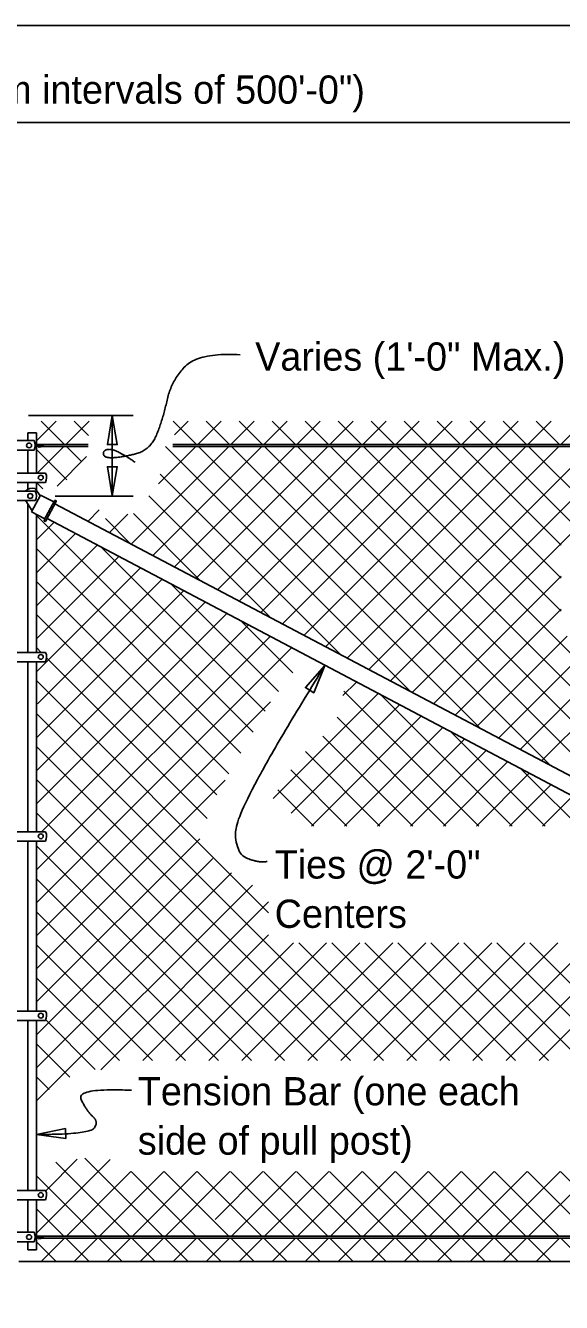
# Model space of a CAD drawing. Extents: x 0 to 72.1, y -7 to 30.
# Drawn here: x 12.41 to 16.24, y 18.9 to 28.01 of the extents above; entities that cross this region are included whole.
import ezdxf

# ---------------------------------------------------------------- set-up
doc = ezdxf.new("R2010")
doc.units = 0
for name, color, linetype in [('ActivePts-ConstElements', 7, 'Continuous'), ('AdhocPoint_dp', 7, 'Continuous'), ('Border', 7, 'Continuous'), ('PlotBorder_dp', 7, 'Continuous'), ('TextMisc', 7, 'Continuous'), ('TextStructures', 7, 'Continuous')]:
    doc.layers.add(name, color=color, linetype=linetype)

msp = doc.modelspace()

# ---------------------------------------------------------------- linework, layer by layer
at = {"layer": 'ActivePts-ConstElements'}
msp.add_lwpolyline([(0.016, 2.0538), (41.2266, 2.0538), (41.2266, 28.0138), (0.016, 28.0138)], close=True, dxfattribs=at)
at = {"layer": 'AdhocPoint_dp'}
for p, q in [((12.4931, 25.0498), (12.6332, 25.1899)), ((12.5258, 25.1899), (12.6924, 25.0233)), ((12.7022, 25.0233), (12.8689, 25.1899)), ((12.7615, 25.1899), (12.8637, 25.0877)), ((13.4686, 25.1899), (13.6352, 25.0233)), ((13.479, 25.0929), (13.576, 25.1899)), ((13.645, 25.0233), (13.8117, 25.1899)), ((13.7043, 25.1899), (13.8709, 25.0233)), ((13.8807, 25.0233), (14.0474, 25.1899)), ((13.94, 25.1899), (14.1066, 25.0233)), ((14.1164, 25.0233), (14.2831, 25.1899)), ((14.1757, 25.1899), (14.3423, 25.0233)), ((14.3521, 25.0233), (14.5188, 25.1899)), ((14.4114, 25.1899), (14.578, 25.0233)), ((14.5878, 25.0233), (14.7545, 25.1899)), ((14.6471, 25.1899), (14.8137, 25.0233)), ((14.8236, 25.0233), (14.9902, 25.1899)), ((14.8828, 25.1899), (15.0494, 25.0233)), ((15.0593, 25.0233), (15.2259, 25.1899)), ((15.1185, 25.1899), (15.2851, 25.0233)), ((15.295, 25.0233), (15.4616, 25.1899)), ((15.3542, 25.1899), (15.5208, 25.0233)), ((15.5307, 25.0233), (15.6973, 25.1899)), ((15.5899, 25.1899), (15.7565, 25.0233)), ((15.7664, 25.0233), (15.933, 25.1899)), ((15.8256, 25.1899), (15.9923, 25.0233)), ((16.0021, 25.0233), (16.1687, 25.1899)), ((16.0613, 25.1899), (16.228, 25.0233)), ((16.2378, 25.0233), (16.4044, 25.1899)), ((12.4931, 24.9869), (12.7098, 24.7702)), ((12.4981, 24.8191), (12.6875, 25.0085)), ((12.7072, 25.0085), (12.8158, 24.8999)), ((13.1697, 24.3123), (13.866, 25.0085)), ((13.3239, 24.2308), (14.1017, 25.0085)), ((13.3647, 24.743), (13.6303, 25.0085)), ((13.4143, 25.0085), (15.1649, 23.2579)), ((13.4782, 24.1493), (14.3374, 25.0085)), ((13.6324, 24.0678), (14.5731, 25.0085)), ((13.65, 25.0085), (15.6647, 22.9938)), ((13.7866, 23.9863), (14.8088, 25.0085)), ((13.8857, 25.0085), (16.1646, 22.7296)), ((13.9408, 23.9048), (15.0445, 25.0085)), ((14.095, 23.8233), (15.2802, 25.0085)), ((14.1214, 25.0085), (16.6644, 22.4655)), ((14.2492, 23.7418), (15.5159, 25.0085)), ((14.3571, 25.0085), (17.1643, 22.2013)), ((14.4034, 23.6603), (15.7516, 25.0085)), ((14.5576, 23.5788), (15.9873, 25.0085)), ((14.5928, 25.0085), (17.4733, 22.128)), ((14.7118, 23.4973), (16.223, 25.0085)), ((14.8285, 25.0085), (17.4733, 22.3637)), ((14.866, 23.4158), (16.4587, 25.0085)), ((15.0203, 23.3343), (16.6944, 25.0085)), ((15.0642, 25.0085), (16.24, 23.8327)), ((15.1745, 23.2529), (16.9301, 25.0085)), ((15.2999, 25.0085), (16.24, 24.0684)), ((15.5356, 25.0085), (16.24, 24.3041)), ((15.7713, 25.0085), (16.409, 24.3708)), ((16.007, 25.0085), (16.6447, 24.3708)), ((12.641, 24.7264), (12.8508, 24.9361)), ((13.3756, 24.8115), (14.665, 23.5221)), ((12.4931, 24.7512), (12.5385, 24.7057)), ((13.2948, 24.6565), (14.1652, 23.7862)), ((12.8613, 24.4752), (12.9417, 24.5557)), ((13.0155, 24.3938), (13.1461, 24.5243)), ((13.1859, 24.5298), (13.6653, 24.0504)), ((12.4931, 24.5155), (14.0393, 22.9693)), ((12.4931, 24.3427), (12.6184, 24.468)), ((12.9848, 24.4952), (13.1655, 24.3145)), ((12.4931, 24.107), (12.7726, 24.3865)), ((12.4931, 23.8713), (12.9268, 24.305)), ((12.4931, 24.2798), (13.9529, 22.8199)), ((12.9533, 24.291), (14.1256, 23.1186)), ((12.4931, 23.6356), (13.081, 24.2235)), ((12.4931, 23.3999), (13.2352, 24.142)), ((15.3287, 23.1714), (16.24, 24.0827)), ((12.4931, 24.0441), (13.8666, 22.6706)), ((12.4931, 22.9285), (13.5436, 23.979)), ((12.4995, 23.1707), (13.3894, 24.0605)), ((13.4531, 24.0268), (14.2202, 23.2598)), ((12.4931, 22.6928), (13.6978, 23.8975)), ((12.4931, 22.4571), (13.852, 23.8161)), ((12.4931, 23.8084), (13.7802, 22.5212)), ((15.4829, 23.0899), (16.24, 23.847)), ((12.5298, 22.2581), (14.0062, 23.7346)), ((13.953, 23.7627), (14.3227, 23.393)), ((12.4931, 21.9857), (14.1605, 23.6531)), ((14.5333, 23.6538), (14.665, 23.5221)), ((15.6371, 23.0084), (16.2825, 23.6538)), ((15.7913, 22.9269), (16.5182, 23.6538)), ((15.7913, 22.9269), (16.5182, 23.6538)), ((15.9455, 22.8454), (16.7539, 23.6538)), ((15.9455, 22.8454), (16.7539, 23.6538)), ((16.0997, 22.7639), (16.9896, 23.6538)), ((16.0997, 22.7639), (16.9896, 23.6538)), ((12.4931, 23.5727), (12.5272, 23.5386)), ((12.4931, 21.75), (14.3147, 23.5716)), ((12.5654, 23.5003), (13.7129, 22.3529)), ((12.4931, 23.337), (14.1505, 21.6795)), ((14.6803, 23.2301), (14.7773, 23.3271)), ((14.6886, 23.2628), (15.6525, 22.2989)), ((12.4931, 21.5143), (14.1643, 23.1855)), ((14.1818, 22.4959), (14.9315, 23.2456)), ((14.3113, 22.3897), (15.0857, 23.1641)), ((14.9526, 23.2344), (15.8882, 22.2989)), ((12.4931, 23.1013), (14.9705, 20.6239)), ((14.4562, 22.2989), (15.2399, 23.0826)), ((14.6408, 23.0749), (15.4168, 22.2989)), ((14.6919, 22.2989), (15.3941, 23.0011)), ((14.5385, 22.9415), (15.1811, 22.2989)), ((14.9276, 22.2989), (15.5484, 22.9196)), ((15.4525, 22.9703), (16.1239, 22.2989)), ((12.4931, 22.8656), (14.7347, 20.6239)), ((14.4136, 22.8307), (14.9454, 22.2989)), ((15.1633, 22.2989), (15.7026, 22.8382)), ((15.399, 22.2989), (15.8568, 22.7567)), ((15.9523, 22.7062), (19.2871, 19.3714)), ((12.4931, 22.6299), (14.499, 20.6239)), ((12.4931, 21.2786), (13.8413, 22.6268)), ((14.3091, 22.6995), (14.7097, 22.2989)), ((15.6347, 22.2989), (16.011, 22.6752)), ((14.2153, 22.5576), (14.474, 22.2989)), ((15.8704, 22.2989), (16.1652, 22.5937)), ((16.1061, 22.2989), (16.3194, 22.5122)), ((12.4931, 22.3942), (14.2633, 20.6239)), ((12.4931, 21.0429), (13.6583, 22.2081)), ((12.4931, 22.1585), (14.0276, 20.6239)), ((12.4931, 20.8072), (13.753, 22.0671)), ((15.6097, 20.6239), (17.0905, 22.1047)), ((15.8454, 20.6239), (17.2447, 22.0232)), ((12.4931, 20.5715), (13.8858, 21.9642)), ((12.4931, 21.9228), (13.7919, 20.6239)), ((16.0811, 20.6239), (17.3989, 21.9417)), ((12.4931, 20.3358), (14.0345, 21.8772)), ((12.9521, 20.5591), (14.1505, 21.7575)), ((12.4931, 21.6871), (13.5562, 20.6239)), ((13.2526, 20.6239), (14.1505, 21.5218)), ((12.4931, 21.4514), (13.3205, 20.6239)), ((13.4883, 20.6239), (14.3292, 21.4647)), ((13.724, 20.6239), (14.5649, 21.4647)), ((13.9597, 20.6239), (14.8006, 21.4647)), ((14.1954, 20.6239), (15.0363, 21.4647)), ((14.3653, 21.4647), (15.2062, 20.6239)), ((14.4311, 20.6239), (15.272, 21.4647)), ((14.601, 21.4647), (15.4419, 20.6239)), ((14.6668, 20.6239), (15.5077, 21.4647)), ((14.8367, 21.4647), (15.6776, 20.6239)), ((14.9025, 20.6239), (15.7434, 21.4647)), ((15.0724, 21.4647), (15.9133, 20.6239)), ((15.1382, 20.6239), (15.9791, 21.4647)), ((15.3081, 21.4647), (16.149, 20.6239)), ((15.3739, 20.6239), (16.2148, 21.4647)), ((15.5438, 21.4647), (16.3847, 20.6239)), ((15.7795, 21.4647), (17.8729, 19.3714)), ((16.0152, 21.4647), (18.1086, 19.3714)), ((12.4931, 21.2157), (13.0848, 20.6239)), ((12.5589, 20.9142), (12.913, 20.56)), ((12.4931, 20.7443), (12.731, 20.5064)), ((12.4931, 20.5086), (12.5834, 20.4182)), ((12.4931, 19.393), (13.0188, 19.9187)), ((12.5588, 19.6944), (12.7844, 19.9199)), ((12.6321, 19.8981), (13.1589, 19.3714)), ((12.8383, 19.9277), (13.3946, 19.3714)), ((12.4931, 19.8015), (12.9232, 19.3714)), ((12.7072, 19.3714), (13.1673, 19.8315)), ((12.9429, 19.3714), (13.403, 19.8315)), ((13.1701, 19.8315), (13.6303, 19.3714)), ((13.1786, 19.3714), (13.6387, 19.8315)), ((13.4058, 19.8315), (13.866, 19.3714)), ((13.4143, 19.3714), (13.8744, 19.8315)), ((13.6415, 19.8315), (14.1017, 19.3714)), ((13.7678, 19.4892), (14.1101, 19.8315)), ((13.8772, 19.8315), (14.3374, 19.3714)), ((13.8857, 19.3714), (14.3459, 19.8315)), ((14.1129, 19.8315), (14.5731, 19.3714)), ((14.1214, 19.3714), (14.5816, 19.8315)), ((14.3486, 19.8315), (14.8088, 19.3714)), ((14.3571, 19.3714), (14.8173, 19.8315)), ((14.5843, 19.8315), (15.0445, 19.3714)), ((14.5928, 19.3714), (15.053, 19.8315)), ((14.82, 19.8315), (15.2802, 19.3714)), ((14.8285, 19.3714), (15.2887, 19.8315)), ((15.0557, 19.8315), (15.5159, 19.3714)), ((15.0642, 19.3714), (15.5244, 19.8315)), ((15.2914, 19.8315), (15.7516, 19.3714)), ((15.2999, 19.3714), (15.7601, 19.8315)), ((15.5271, 19.8315), (15.9873, 19.3714)), ((15.5356, 19.3714), (15.9958, 19.8315)), ((15.7628, 19.8315), (16.223, 19.3714)), ((15.7713, 19.3714), (16.2315, 19.8315)), ((15.9985, 19.8315), (16.4587, 19.3714)), ((16.007, 19.3714), (16.4663, 19.8306)), ((16.2343, 19.8315), (16.6944, 19.3714)), ((12.4931, 19.5658), (12.6875, 19.3714)), ((12.4931, 19.3301), (12.6332, 19.1899)), ((12.5258, 19.1899), (12.6924, 19.3566)), ((12.7022, 19.3566), (12.8689, 19.1899)), ((12.7615, 19.1899), (12.9281, 19.3566)), ((12.9379, 19.3566), (13.1046, 19.1899)), ((12.9972, 19.1899), (13.1638, 19.3566)), ((13.1736, 19.3566), (13.3403, 19.1899)), ((13.2329, 19.1899), (13.3995, 19.3566)), ((13.4093, 19.3566), (13.576, 19.1899)), ((13.4686, 19.1899), (13.6352, 19.3566)), ((13.645, 19.3566), (13.8117, 19.1899)), ((13.7043, 19.1899), (13.8709, 19.3566)), ((13.8807, 19.3566), (14.0474, 19.1899)), ((13.94, 19.1899), (14.1066, 19.3566)), ((14.1164, 19.3566), (14.2831, 19.1899)), ((14.1757, 19.1899), (14.3423, 19.3566)), ((14.3521, 19.3566), (14.5188, 19.1899)), ((14.4114, 19.1899), (14.578, 19.3566)), ((14.5878, 19.3566), (14.7545, 19.1899)), ((14.6471, 19.1899), (14.8137, 19.3566)), ((14.8236, 19.3566), (14.9902, 19.1899)), ((14.8828, 19.1899), (15.0494, 19.3566)), ((15.0593, 19.3566), (15.2259, 19.1899)), ((15.1185, 19.1899), (15.2851, 19.3566)), ((15.295, 19.3566), (15.4616, 19.1899)), ((15.3542, 19.1899), (15.5208, 19.3566)), ((15.5307, 19.3566), (15.6973, 19.1899)), ((15.5899, 19.1899), (15.7565, 19.3566)), ((15.7664, 19.3566), (15.933, 19.1899)), ((15.8256, 19.1899), (15.9923, 19.3566)), ((16.0021, 19.3566), (16.1687, 19.1899)), ((16.0613, 19.1899), (16.228, 19.3566)), ((16.2378, 19.3566), (16.4044, 19.1899))]:
    msp.add_line(p, q, dxfattribs=at)
at = {"layer": 'Border'}
for p, q in [((2.2222, 27.321), (22.2222, 27.321)), ((13.1844, 25.2299), (12.4354, 25.2299)), ((13.0344, 24.655), (13.0344, 25.2299)), ((13.1844, 24.655), (12.6254, 24.655))]:
    msp.add_line(p, q, dxfattribs=at)
for points in [[(13.0345, 25.2299), (12.9992, 25.0216), (13.0697, 25.0216)], [(13.0345, 24.6551), (13.0697, 24.8633), (12.9992, 24.8633)], [(14.5522, 23.446), (14.4131, 23.287), (14.4732, 23.2501)], [(12.4931, 20.0967), (12.7023, 20.0677), (12.7002, 20.1382)]]:
    msp.add_lwpolyline(points, close=True, dxfattribs=at)
for points in [[(13.9481, 25.6637), (13.65, 25.6797), (13.4553, 25.4772), (13.3956, 25.2009), (13.3033, 24.979), (13.0818, 24.9282), (12.9711, 24.9282), (12.9711, 24.9882), (13.0634, 24.9882), (13.1972, 24.8959)], [(14.1404, 22.0465), (14.0937, 22.0323), (13.9108, 22.0996), (13.9193, 22.4262), (14.5522, 23.4461)], [(13.1705, 20.4124), (12.7718, 20.4303), (12.8521, 20.2635), (12.9384, 20.186), (12.87, 20.0967), (12.4931, 20.0967)]]:
    msp.add_open_spline(points, degree=2, dxfattribs=at)
at = {"layer": 'PlotBorder_dp'}
for p, q in [((12.4306, 25.0504), (12.4306, 25.1066)), ((12.4306, 25.1066), (12.4931, 25.1066)), ((12.4306, 25.0504), (12.4306, 25.1066)), ((12.4306, 25.1066), (12.4931, 25.1066)), ((12.4931, 25.0264), (12.4931, 25.1066)), ((12.4931, 25.0264), (12.4931, 25.1066)), ((12.0665, 25.0504), (12.4762, 25.0504)), ((12.0665, 24.9827), (12.4759, 24.9827)), ((12.4306, 24.9826), (12.4306, 24.8191)), ((12.4306, 24.9826), (12.4306, 24.8191)), ((12.4835, 25.0279), (12.5128, 25.0233)), ((12.4836, 25.0279), (12.5129, 25.0233)), ((12.484, 25.0075), (12.5177, 25.0131)), ((12.4841, 25.0229), (12.5102, 25.0189)), ((12.4841, 25.0075), (12.5178, 25.0131)), ((12.4842, 25.0229), (12.5103, 25.0189)), ((12.4845, 25.0123), (12.5143, 25.0172)), ((12.4846, 25.0123), (12.5145, 25.0172)), ((12.4931, 25.0215), (12.4931, 25.0136)), ((12.4931, 25.0215), (12.4931, 25.0136)), ((12.4931, 25.009), (12.4931, 24.8191)), ((12.4931, 25.009), (12.4931, 24.8191)), ((12.5041, 25.0085), (12.8633, 25.0085)), ((12.5054, 25.0233), (12.8633, 25.0233)), ((13.4663, 25.0233), (21.9013, 25.0233)), ((13.4663, 25.0085), (21.9279, 25.0085)), ((12.0665, 24.8192), (12.5576, 24.8192)), ((12.0665, 24.7516), (12.5568, 24.7516)), ((12.4306, 24.7025), (12.4306, 24.7515)), ((12.5188, 24.6556), (12.484, 24.7087)), ((12.4931, 24.6949), (12.4931, 24.7515)), ((11.9599, 24.6896), (12.4847, 24.6896)), ((11.9599, 24.6218), (12.4847, 24.6218)), ((12.4627, 24.5496), (12.4159, 24.6213)), ((12.5222, 24.6621), (12.4585, 24.5416)), ((12.5222, 24.6621), (12.6165, 24.6123)), ((12.6211, 24.6209), (12.5487, 24.4838)), ((12.633, 24.6147), (12.5605, 24.4776)), ((12.4306, 23.5386), (12.4306, 24.5988)), ((12.5528, 24.4917), (12.4585, 24.5416)), ((12.4931, 23.5386), (12.4931, 24.5233)), ((21.8748, 19.712), (12.6252, 24.6)), ((21.8189, 19.606), (12.5692, 24.494)), ((12.4306, 23.5386), (12.4306, 24.1039)), ((12.4931, 23.5386), (12.4931, 24.0693)), ((12.0665, 23.5386), (12.5576, 23.5386)), ((12.0665, 23.471), (12.5568, 23.471)), ((12.4306, 22.2581), (12.4306, 23.471)), ((12.4931, 22.2581), (12.4931, 23.471)), ((12.0665, 22.2581), (12.5576, 22.2581)), ((12.0665, 22.1905), (12.5568, 22.1905)), ((12.4306, 20.9776), (12.4306, 22.1905)), ((12.4931, 20.9776), (12.4931, 22.1905)), ((12.0665, 20.9776), (12.5576, 20.9776)), ((12.0665, 20.91), (12.5568, 20.91)), ((12.4306, 19.6971), (12.4306, 20.9099)), ((12.4931, 19.6971), (12.4931, 20.9099)), ((12.0665, 19.6972), (12.5576, 19.6972)), ((12.0665, 19.6295), (12.5568, 19.6295)), ((12.4306, 19.6295), (12.4306, 19.3985)), ((12.4931, 19.3745), (12.4931, 19.6295)), ((11.9684, 19.3985), (12.4762, 19.3985)), ((11.9686, 19.3307), (12.4759, 19.3307)), ((12.4306, 19.3307), (12.4306, 19.2733)), ((12.4835, 19.376), (12.5128, 19.3715)), ((12.4836, 19.376), (12.5129, 19.3715)), ((12.484, 19.3556), (12.5177, 19.3613)), ((12.4841, 19.3709), (12.5102, 19.3669)), ((12.4841, 19.3556), (12.5178, 19.3613)), ((12.4842, 19.3709), (12.5103, 19.3669)), ((12.4845, 19.3603), (12.5143, 19.3653)), ((12.4846, 19.3603), (12.5145, 19.3653)), ((12.4931, 19.3617), (12.4931, 19.3695)), ((12.4931, 19.3617), (12.4931, 19.3695)), ((12.4931, 19.2733), (12.4931, 19.3571)), ((12.5301, 19.3566), (21.9279, 19.3566)), ((12.5315, 19.3714), (21.9013, 19.3714)), ((12.4306, 19.2733), (12.4931, 19.2733))]:
    msp.add_line(p, q, dxfattribs=at)
for centre, start, end in [((12.6269, 24.6177), 332.14902, 152.14902), ((12.5544, 24.4805), 152.14902, 332.14902)]:
    msp.add_arc(centre, 0.00673, start, end, dxfattribs=at)
for centre, major_axis in [((12.4402, 25.0159), (-0.0178, 0)), ((12.4402, 25.0159), (-0.0178, 0)), ((12.5239, 24.7864), (-0.0177, 0)), ((12.5239, 24.7864), (-0.0177, 0)), ((12.4488, 24.655), (-0.0178, 0)), ((12.5239, 23.5059), (-0.0177, 0)), ((12.5239, 23.5059), (-0.0177, 0)), ((12.5239, 22.2254), (-0.0177, 0)), ((12.5239, 22.2254), (-0.0177, 0)), ((12.5239, 20.9449), (-0.0177, 0)), ((12.5239, 20.9449), (-0.0177, 0)), ((12.5239, 19.6644), (-0.0177, 0)), ((12.4402, 19.364), (-0.0178, 0)), ((12.4402, 19.364), (-0.0178, 0))]:
    msp.add_ellipse(centre, major_axis=major_axis, ratio=0.957868, dxfattribs=at)
for centre, major_axis, ratio, start_param, end_param in [((12.4069, 25.0168), (0.0776, 0), 0.957868, 5.803915, 6.752041), ((12.4069, 25.0168), (0.0776, 0), 0.957868, 5.803915, 6.752041), ((12.5153, 25.0135), (-0.0095, 0), 0.957868, 5.673972, 6.052579), ((12.5153, 25.0135), (-0.0095, 0), 0.957868, 5.673972, 6.052579), ((12.5153, 25.0135), (-0.0095, 0), 0.957868, 0.252467, 1.271421), ((12.5153, 25.0135), (-0.0095, 0), 0.957868, 0.252467, 1.271421), ((12.5094, 25.0093), (0.00982, 0), 0.957868, 0.655696, 1.505671), ((12.5094, 25.0093), (0.00982, 0), 0.957868, 0.655696, 1.505671), ((12.5114, 25.0142), (0.0115, -0.0041), 0.737732, 5.08821, 8.212701), ((12.5114, 25.0142), (0.0115, -0.0041), 0.737732, 5.08821, 8.212701), ((12.5148, 25.0117), (0.00301, 0), 0.957868, 3.28349, 5.170635), ((12.5148, 25.0117), (0.00301, 0), 0.957868, 3.28349, 5.170635), ((12.5154, 25.0139), (-0.00453, 0), 0.957868, 5.149727, 5.551998), ((12.5154, 25.0139), (-0.00453, 0), 0.957868, 5.149727, 5.551998), ((12.5126, 25.0126), (0.00527, 0), 0.957868, 5.058829, 7.342751), ((12.5126, 25.0126), (0.00527, 0), 0.957868, 5.058829, 7.342751), ((12.517, 25.015), (-0.00872, 0), 0.957868, 2.1008, 4.992926), ((12.517, 25.015), (-0.00872, 0), 0.957868, 2.1008, 4.992926), ((12.5148, 25.0117), (0.00301, 0), 0.957868, 0.004594, 0.141897), ((12.5148, 25.0117), (0.00301, 0), 0.957868, 0.004594, 0.141897), ((12.5231, 25.0146), (0.00944, 0), 0.957868, 4.316497, 6.557353), ((12.5231, 25.0146), (0.00944, 0), 0.957868, 4.316497, 6.557353), ((12.5236, 25.0155), (-0.00872, 0), 0.957868, 3.323334, 4.992926), ((12.5236, 25.0155), (-0.00872, 0), 0.957868, 3.323334, 4.992926), ((12.5236, 25.0155), (-0.00503, 0), 0.92697, 1.780895, 4.712389), ((12.5236, 25.0155), (-0.00503, 0), 0.92697, 1.780895, 4.712389), ((12.5283, 25.01), (-0.0142, 0), 0.957868, 3.141593, 4.79635), ((12.5283, 25.01), (-0.0142, 0), 0.957868, 3.141593, 4.79635), ((12.5203, 24.995), (0.0274, 0), 0.957868, 0.628521, 1.149654), ((12.5203, 24.995), (0.0274, 0), 0.957868, 0.628521, 1.149654), ((12.488, 24.786), (0.0776, 0), 0.957868, 5.801244, 6.745158), ((12.488, 24.786), (0.0776, 0), 0.957868, 5.801244, 6.745158), ((12.4674, 24.6404), (-0.0647, 0.0342), 0.957868, 4.95193, 6.011789), ((12.4154, 24.6554), (0.0776, 0), 0.957868, 5.810211, 6.75616), ((12.488, 23.5055), (0.0776, 0), 0.957868, 5.801046, 6.744962), ((12.488, 23.5055), (0.0776, 0), 0.957868, 5.801046, 6.744962), ((12.488, 22.225), (0.0776, 0), 0.957868, 5.800848, 6.744767), ((12.488, 22.225), (0.0776, 0), 0.957868, 5.800848, 6.744767), ((12.488, 20.9444), (0.0776, 0), 0.957868, 5.810211, 6.745158), ((12.488, 20.9444), (0.0776, 0), 0.957868, 5.810211, 6.745158), ((12.488, 19.664), (0.0776, 0), 0.957868, 5.800651, 6.745353), ((12.4069, 19.3649), (0.0776, 0), 0.957868, 5.803915, 6.752041), ((12.4069, 19.3649), (0.0776, 0), 0.957868, 5.803915, 6.752041), ((12.5153, 19.3615), (-0.0095, 0), 0.957868, 5.673972, 6.052579), ((12.5153, 19.3615), (-0.0095, 0), 0.957868, 5.673972, 6.052579), ((12.5153, 19.3615), (-0.0095, 0), 0.957868, 0.252467, 1.271421), ((12.5153, 19.3615), (-0.0095, 0), 0.957868, 0.252467, 1.271421), ((12.5094, 19.3574), (0.00982, 0), 0.957868, 0.655696, 1.505671), ((12.5094, 19.3574), (0.00982, 0), 0.957868, 0.655696, 1.505671), ((12.5114, 19.3623), (0.0115, -0.0041), 0.737732, 5.08821, 8.212701), ((12.5114, 19.3623), (0.0115, -0.0041), 0.737732, 5.08821, 8.212701), ((12.5148, 19.3598), (0.00301, 0), 0.957868, 3.28349, 5.170635), ((12.5148, 19.3598), (0.00301, 0), 0.957868, 3.28349, 5.170635), ((12.5154, 19.362), (-0.00453, 0), 0.957868, 5.149727, 5.551998), ((12.5154, 19.362), (-0.00453, 0), 0.957868, 5.149727, 5.551998), ((12.5126, 19.3607), (0.00527, 0), 0.957868, 5.058829, 7.342751), ((12.5126, 19.3607), (0.00527, 0), 0.957868, 5.058829, 7.342751), ((12.517, 19.3631), (-0.00872, 0), 0.957868, 2.1008, 4.992926), ((12.517, 19.3631), (-0.00872, 0), 0.957868, 2.1008, 4.992926), ((12.5148, 19.3598), (0.00301, 0), 0.957868, 0.004594, 0.141897), ((12.5148, 19.3598), (0.00301, 0), 0.957868, 0.004594, 0.141897), ((12.5231, 19.3627), (0.00944, 0), 0.957868, 4.316497, 6.557353), ((12.5231, 19.3627), (0.00944, 0), 0.957868, 4.316497, 6.557353), ((12.5236, 19.3636), (-0.00872, 0), 0.957868, 3.323334, 4.992926), ((12.5236, 19.3636), (-0.00872, 0), 0.957868, 3.323334, 4.992926), ((12.5236, 19.3636), (-0.00503, 0), 0.92697, 1.780895, 4.712389), ((12.5236, 19.3636), (-0.00503, 0), 0.92697, 1.780895, 4.712389), ((12.5283, 19.3581), (-0.0142, 0), 0.957868, 3.141593, 4.79635), ((12.5283, 19.3581), (-0.0142, 0), 0.957868, 3.141593, 4.79635), ((12.5203, 19.3431), (0.0274, 0), 0.957868, 0.628521, 1.149654), ((12.5203, 19.3431), (0.0274, 0), 0.957868, 0.628521, 1.149654)]:
    msp.add_ellipse(centre, major_axis=major_axis, ratio=ratio, start_param=start_param, end_param=end_param, dxfattribs=at)
at = {"layer": 'TextMisc'}
msp.add_line((12.3681, 19.1899), (18.8364, 19.1899), dxfattribs=at)

# ---------------------------------------------------------------- texts
at = {"layer": 'TextStructures'}
for s, p in [('Pull Post Assembly (required at maximum intervals of 500\'-0")', (7.4543, 27.4558)), ('Varies (1\'-0" Max.)  (Typ.)', (14.0546, 25.5501)), ('Ties @ 2\'-0" ', (14.1939, 21.9237)), ('Centers', (14.1939, 21.5717)), ('Tension Bar (one each ', (13.2165, 20.3047)), ('side of pull post)', (13.2165, 19.9527))]:
    msp.add_text(s, height=0.2016, dxfattribs=at).set_placement(p)

doc.saveas('drawing.dxf')
